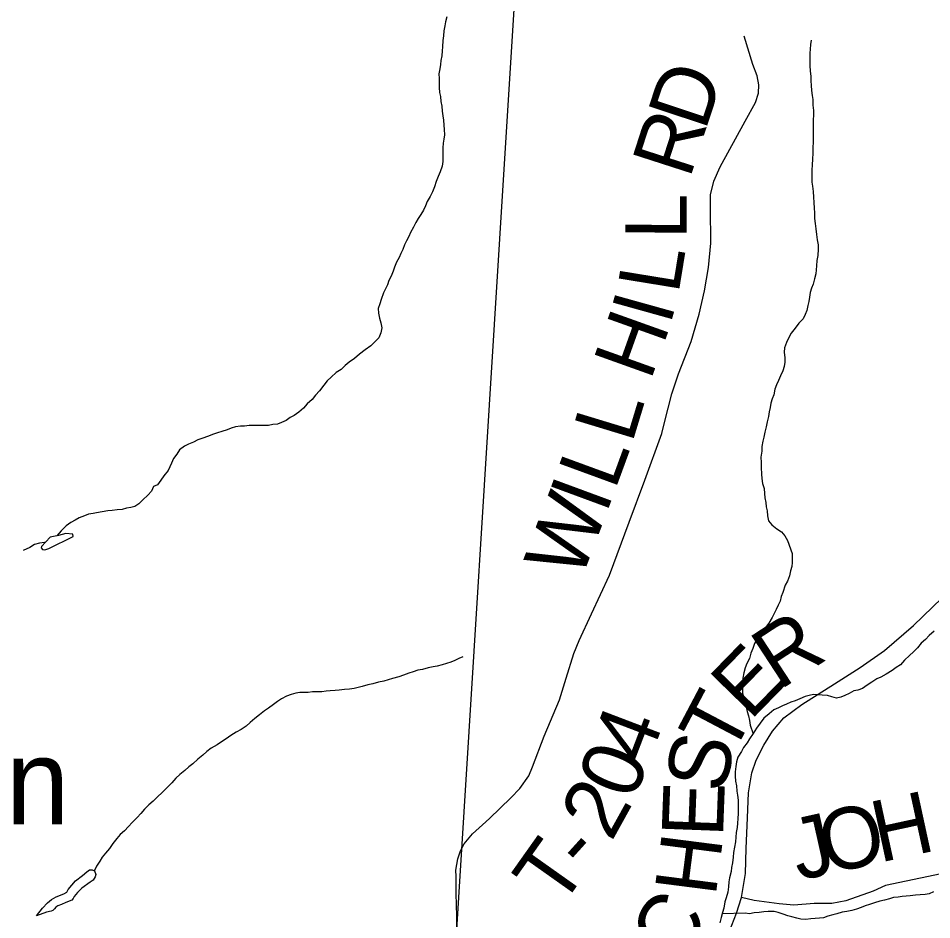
# Model space of a CAD drawing. Extents: x -20.2 to 34, y 0 to 22.
# Drawn here: x 6.324 to 7.17, y 14.988 to 15.823 of the extents above; entities that cross this region are included whole.
import ezdxf

# ---------------------------------------------------------------- set-up
doc = ezdxf.new("R2010")
doc.units = 0
for name, color, linetype in [('GM_X_County_Road_Text', 7, 'Continuous'), ('GM_X_Minor_River', 7, 'Continuous'), ('GM_X_Section', 7, 'Continuous'), ('GM_X_State_Route', 7, 'Continuous'), ('GM_X_Township_Road', 7, 'Continuous'), ('GM_X_Township_Road_Text', 7, 'Continuous'), ('GM_X_Unincorporated_Text', 7, 'Continuous')]:
    doc.layers.add(name, color=color, linetype=linetype)

msp = doc.modelspace()

# ---------------------------------------------------------------- linework, layer by layer
at = {"layer": 'GM_X_Minor_River'}
for points in [[(6.72087, 15.82416), (6.71976, 15.81959), (6.71903, 15.81579), (6.7183, 15.81123), (6.71796, 15.80667), (6.71723, 15.80211), (6.71689, 15.79641), (6.71654, 15.79261), (6.71619, 15.78805), (6.71546, 15.78386), (6.71511, 15.78006), (6.71439, 15.77588), (6.71366, 15.77132), (6.71369, 15.76714), (6.71372, 15.76258), (6.71375, 15.75879), (6.71416, 15.75423), (6.71495, 15.75044), (6.71536, 15.74588), (6.71616, 15.74133), (6.71657, 15.73678), (6.71736, 15.73261)], [(7.05821, 15.80264), (7.05749, 15.79846), (7.05714, 15.79428), (7.05678, 15.79048), (7.05681, 15.78668), (7.05684, 15.78251), (7.05687, 15.77871), (7.05728, 15.77415), (7.0577, 15.76884), (7.05773, 15.76504), (7.05814, 15.76049), (7.05856, 15.75593), (7.05897, 15.75138), (7.05976, 15.74759), (7.0598, 15.74227), (7.06021, 15.73733), (7.06024, 15.73354), (7.0599, 15.7286), (7.05994, 15.72214), (7.05998, 15.7172), (7.06001, 15.71303), (7.06005, 15.70771), (7.0597, 15.70353), (7.05974, 15.69783), (7.0594, 15.69251), (7.05906, 15.68719), (7.05872, 15.68225), (7.05876, 15.67694), (7.0588, 15.67124), (7.05921, 15.66744), (7.06, 15.66251), (7.06042, 15.6572), (7.06046, 15.65226), (7.06088, 15.64695), (7.06129, 15.64277), (7.06133, 15.63745), (7.06174, 15.6329), (7.06254, 15.62797), (7.06295, 15.62265), (7.06375, 15.61772), (7.06454, 15.61317), (7.06457, 15.60899), (7.06424, 15.60329), (7.06351, 15.59873), (7.06317, 15.59379), (7.06281, 15.58999), (7.06246, 15.58619), (7.06136, 15.58162), (7.05988, 15.57667), (7.05839, 15.57286), (7.05727, 15.56906), (7.05655, 15.56449), (7.05582, 15.56069), (7.05508, 15.55689), (7.05398, 15.55232), (7.05249, 15.54851), (7.05062, 15.5447), (7.04685, 15.54049), (7.04347, 15.53591), (7.0397, 15.53133), (7.03708, 15.52675), (7.03521, 15.52256), (7.03335, 15.51761), (7.033, 15.51381), (7.0338, 15.5085), (7.03383, 15.50432), (7.0331, 15.50051), (7.03199, 15.49633), (7.02974, 15.49175), (7.02787, 15.48756), (7.02601, 15.48337), (7.02452, 15.47956), (7.02342, 15.47423), (7.02193, 15.47043), (7.02082, 15.46662), (7.02009, 15.46244), (7.01935, 15.45863), (7.01863, 15.45407), (7.01753, 15.44912), (7.01642, 15.44456), (7.01532, 15.43961), (7.01421, 15.43505), (7.01348, 15.43124), (7.01238, 15.42629), (7.01241, 15.42212), (7.01169, 15.41642), (7.01173, 15.41148), (7.01176, 15.40692), (7.01219, 15.40084), (7.0126, 15.39667), (7.01301, 15.39211), (7.01456, 15.38757), (7.01498, 15.38301), (7.01539, 15.37883), (7.01618, 15.37466), (7.01659, 15.37049), (7.01738, 15.36669), (7.01779, 15.36214), (7.01858, 15.35759), (7.02165, 15.35381), (7.02623, 15.35004)], [(6.71736, 15.73261), (6.71777, 15.72843), (6.71818, 15.72388), (6.71859, 15.7197), (6.71863, 15.71476), (6.71828, 15.71096), (6.71755, 15.70716), (6.7172, 15.70298), (6.71723, 15.6988), (6.71726, 15.69462), (6.71729, 15.69007), (6.71656, 15.68588), (6.71471, 15.68055), (6.71284, 15.67636), (6.71097, 15.67179), (6.70949, 15.66684), (6.70762, 15.66227), (6.70538, 15.6577), (6.70275, 15.65312), (6.70126, 15.64931), (6.69939, 15.64512), (6.69677, 15.6413), (6.69452, 15.63749), (6.69227, 15.63368), (6.69002, 15.62948), (6.68739, 15.62453), (6.6859, 15.62071), (6.68365, 15.6169), (6.68178, 15.61309), (6.6803, 15.6089), (6.67843, 15.60509), (6.67694, 15.60128), (6.67431, 15.59708), (6.67244, 15.59251), (6.67133, 15.58871), (6.66947, 15.58414), (6.66722, 15.57994), (6.66611, 15.57614), (6.66424, 15.57232), (6.66237, 15.56851), (6.66013, 15.56242), (6.65902, 15.55861), (6.65754, 15.55404), (6.65757, 15.54987), (6.65874, 15.54532), (6.65991, 15.54077), (6.66071, 15.53621), (6.65998, 15.53165), (6.65811, 15.52708), (6.65435, 15.52325), (6.65058, 15.51943), (6.64529, 15.51597), (6.64, 15.51176), (6.63547, 15.50793), (6.63056, 15.50447), (6.62679, 15.50141), (6.62302, 15.49758), (6.61848, 15.49489), (6.61396, 15.49068), (6.61018, 15.48723), (6.60718, 15.48303), (6.60304, 15.47807), (6.59927, 15.47386), (6.59626, 15.47004), (6.59174, 15.46583), (6.58835, 15.46201), (6.58382, 15.45818), (6.57966, 15.45511), (6.57588, 15.45318), (6.5721, 15.4505), (6.56794, 15.44857), (6.56416, 15.44702), (6.55998, 15.44661), (6.55581, 15.44582), (6.55201, 15.44579), (6.54708, 15.44576), (6.54252, 15.44572), (6.53796, 15.44569), (6.53379, 15.44528), (6.52999, 15.44525), (6.52544, 15.44446), (6.52128, 15.44329), (6.51749, 15.44175), (6.51256, 15.44019), (6.50877, 15.43903), (6.50499, 15.43786), (6.49931, 15.43554), (6.49514, 15.43399), (6.4906, 15.43244), (6.48643, 15.43051), (6.48189, 15.42858), (6.47811, 15.42665), (6.47358, 15.4232), (6.47095, 15.41938), (6.46794, 15.41518), (6.46607, 15.41099), (6.46309, 15.40413), (6.45895, 15.39916), (6.45632, 15.39535), (6.45331, 15.39077), (6.44953, 15.38922)], [(6.44953, 15.38922), (6.44766, 15.38503), (6.44427, 15.38121), (6.43974, 15.377), (6.43598, 15.37317), (6.4322, 15.37086), (6.4284, 15.37008), (6.42461, 15.36929), (6.42044, 15.36812), (6.41589, 15.36771), (6.41134, 15.3673), (6.40716, 15.36689), (6.40189, 15.36591), (6.3967, 15.36508), (6.39351, 15.36451), (6.38934, 15.36372), (6.3856, 15.36225), (6.38063, 15.36024), (6.37685, 15.35831), (6.37307, 15.356), (6.36853, 15.35293), (6.36401, 15.34834), (6.35987, 15.34375), (6.35995, 15.34382)], [(6.37506, 15.3431), (6.37467, 15.34538), (6.36821, 15.34571), (6.36139, 15.34414), (6.3538, 15.34257), (6.34589, 15.33378), (6.34552, 15.33264), (6.34667, 15.33112), (6.34895, 15.33076), (6.35274, 15.33193), (6.37506, 15.3431)], [(7.02623, 15.35004), (7.03081, 15.34742), (7.03387, 15.34364), (7.03618, 15.33948), (7.04045, 15.32735), (7.04048, 15.32317), (7.04051, 15.319), (7.04016, 15.31519), (7.03905, 15.31139), (7.03794, 15.30682), (7.03608, 15.30187), (7.03421, 15.29806), (7.03198, 15.2912), (7.03049, 15.28739), (7.02939, 15.28321), (7.02751, 15.2794), (7.02564, 15.27559), (7.02377, 15.27177), (7.0219, 15.26796), (7.0189, 15.263), (7.01589, 15.2588), (7.01138, 15.25345), (7.008, 15.24811), (7.00575, 15.24391), (7.00427, 15.23934), (7.0024, 15.23515), (7.00092, 15.2302), (6.99867, 15.22563), (6.99718, 15.22144), (6.9957, 15.21687), (6.99498, 15.21193), (6.99464, 15.20699), (6.99467, 15.20281), (6.9947, 15.19825), (6.99549, 15.19446), (6.99666, 15.18953), (6.99783, 15.18497), (6.999, 15.18118), (7.00017, 15.17701), (7.00096, 15.17284), (7.00175, 15.16829), (7.00433, 15.16051)], [(6.34964, 15.33794), (6.34852, 15.3376), (6.34397, 15.3368), (6.33942, 15.33563), (6.33489, 15.33294), (6.32875, 15.33024)], [(7.17199, 15.25536), (7.16746, 15.25153), (7.16407, 15.2477), (7.15992, 15.24425), (7.15653, 15.24005), (7.15276, 15.23623), (7.14899, 15.23278), (7.14446, 15.22857), (7.1407, 15.22436), (7.13692, 15.22168), (7.13314, 15.21899), (7.12747, 15.21553), (7.12256, 15.21284), (7.11877, 15.21129), (7.11424, 15.20822), (7.11008, 15.20553), (7.10555, 15.20246), (7.10138, 15.20091), (7.09759, 15.20012), (7.09343, 15.19781), (7.08927, 15.19589), (7.08548, 15.19434), (7.08169, 15.19355), (7.07712, 15.19466), (7.07332, 15.19577), (7.06838, 15.19612), (7.0642, 15.19647)], [(6.73586, 15.23173), (6.73207, 15.23018), (6.72829, 15.22825), (6.72451, 15.22671), (6.72072, 15.22554), (6.71655, 15.22437), (6.712, 15.2232), (6.70821, 15.22241), (6.70366, 15.22162), (6.69835, 15.22006), (6.69418, 15.21927), (6.68964, 15.21772), (6.68585, 15.21655), (6.68093, 15.21462), (6.67638, 15.21307), (6.6707, 15.2115), (6.66653, 15.21034), (6.66274, 15.20917), (6.65781, 15.20837), (6.65251, 15.20682), (6.64796, 15.20564), (6.64265, 15.20409), (6.63886, 15.2033), (6.63507, 15.20251), (6.6309, 15.20172), (6.62635, 15.20131), (6.62141, 15.20089), (6.61762, 15.20049), (6.61307, 15.20008), (6.60927, 15.20005), (6.6051, 15.19926), (6.6013, 15.19923), (6.59674, 15.1992), (6.59257, 15.19879), (6.58877, 15.19876), (6.58498, 15.19874), (6.58118, 15.19795), (6.57702, 15.19678), (6.57247, 15.19523), (6.56793, 15.19292), (6.56415, 15.19023), (6.56038, 15.18754), (6.55585, 15.18409), (6.55207, 15.18179), (6.54754, 15.17795), (6.54339, 15.1745), (6.53885, 15.17105), (6.53508, 15.16761), (6.53055, 15.16454), (6.52601, 15.16184), (6.5211, 15.15877), (6.51656, 15.1557), (6.51241, 15.15301), (6.50825, 15.15032), (6.50296, 15.14724), (6.4988, 15.14418), (6.49503, 15.14073), (6.4905, 15.1369), (6.48598, 15.13269), (6.4822, 15.13), (6.47843, 15.12655), (6.4739, 15.12272), (6.47013, 15.11927), (6.46636, 15.11507), (6.46222, 15.11086), (6.45769, 15.10627), (6.45279, 15.10168), (6.44902, 15.09823), (6.44525, 15.09478), (6.4411, 15.09057), (6.43771, 15.08675), (6.43432, 15.08293), (6.4298, 15.07834), (6.42641, 15.07451), (6.42264, 15.07069), (6.41849, 15.06724), (6.41548, 15.06342), (6.41172, 15.05883), (6.40872, 15.05425), (6.40495, 15.05005), (6.40194, 15.04623), (6.39969, 15.04241), (6.39669, 15.03783), (6.39482, 15.03402)], [(7.0642, 15.19647), (7.0604, 15.19682), (7.05623, 15.19603), (7.05244, 15.19486), (7.04752, 15.19293), (7.04336, 15.191), (7.03919, 15.18983), (7.03541, 15.1879), (7.03162, 15.18636), (7.02784, 15.18443), (7.02367, 15.1825), (7.01914, 15.17905), (7.01424, 15.17483), (7.01085, 15.17025), (7.00747, 15.16567), (7.00447, 15.16071), (7.00109, 15.15575), (6.99884, 15.15193), (6.99545, 15.14773), (6.99358, 15.14392), (6.9902, 15.13895), (6.9891, 15.13439), (6.98837, 15.1302), (6.98764, 15.12526), (6.98767, 15.12108), (6.98809, 15.11653), (6.98888, 15.11235), (6.9893, 15.10742), (6.99008, 15.10362), (6.9905, 15.09907), (6.99053, 15.09489), (6.99056, 15.09033), (6.99059, 15.08653), (6.99024, 15.08197), (6.98989, 15.07779), (6.98955, 15.07361), (6.98882, 15.06904), (6.98847, 15.06486), (6.98813, 15.0603), (6.98702, 15.05535), (6.9863, 15.05041), (6.98595, 15.04623), (6.98523, 15.0409), (6.9845, 15.03672), (6.98415, 15.03292), (6.98267, 15.02721), (6.98194, 15.02341), (6.9816, 15.01885), (6.98088, 15.0139), (6.9794, 15.00857), (6.97828, 15.00477), (6.97719, 14.99906), (6.97608, 14.99487), (6.97498, 14.9903), (6.97349, 14.98536)], [(6.34121, 14.99185), (6.34685, 14.9991), (6.35137, 15.00407), (6.35514, 15.00714), (6.3593, 15.00945), (6.3665, 15.01216), (6.36915, 15.0137), (6.37064, 15.01637), (6.37742, 15.0244), (6.38384, 15.02938), (6.38764, 15.03269), (6.39026, 15.03437), (6.3926, 15.03446), (6.39482, 15.03364), (6.39599, 15.03023), (6.39562, 15.02795), (6.39375, 15.02489), (6.39072, 15.02297), (6.38317, 15.0176), (6.37902, 15.01339), (6.37601, 15.00995), (6.37526, 15.00804), (6.37376, 15.00651), (6.36846, 15.0042), (6.36429, 15.00227), (6.36096, 15.00104), (6.35907, 15.0001), (6.35787, 14.99842), (6.35623, 14.99691), (6.35485, 14.99612), (6.3503, 14.99533), (6.34121, 14.99185)], [(7.17149, 15.01412), (7.16733, 15.01219), (7.16354, 15.01179), (7.15898, 15.01137), (7.15481, 15.01096), (7.14988, 15.01055), (7.14608, 15.01014), (7.14229, 15.00974), (7.13849, 15.00933), (7.13432, 15.00892), (7.13053, 15.00775), (7.12598, 15.00658), (7.12182, 15.00541), (7.11689, 15.00386), (7.11197, 15.0023), (7.10818, 15.00113), (7.10439, 14.99959), (7.10023, 14.99804), (7.09568, 14.99687), (7.09113, 14.99607), (7.08696, 14.99528), (7.08203, 14.99373), (7.07824, 14.99294), (7.07369, 14.99177), (7.06953, 14.99022), (7.06573, 14.98981), (7.06194, 14.98941), (7.05776, 14.989), (7.05321, 14.98858), (7.04865, 14.98893), (7.04485, 14.98966), (7.04028, 14.99115), (7.03648, 14.99188), (7.03229, 14.99337), (7.02772, 14.99486), (7.02392, 14.99597), (7.01822, 14.99593), (7.01443, 14.99553), (7.00987, 14.99511), (7.00532, 14.9947), (7.00115, 14.99391), (6.99697, 14.99426), (6.9758, 14.99371)]]:
    msp.add_lwpolyline(points, dxfattribs=at)
at = {"layer": 'GM_X_Section'}
msp.add_lwpolyline([(6.79044, 15.94473), (7.86237, 15.87982), (7.79854, 14.87534), (6.72741, 14.93458), (6.77473, 15.69297)], close=True, dxfattribs=at)
at = {"layer": 'GM_X_State_Route'}
for points in [[(6.99364, 15.00887), (6.99749, 15.03099), (6.99811, 15.05429), (6.99915, 15.08279), (6.99998, 15.10567), (7.0031, 15.12418), (7.00727, 15.13605), (7.01434, 15.14977), (7.02224, 15.16288), (7.03285, 15.17515), (7.04949, 15.18764), (7.07966, 15.20656), (7.10358, 15.22175), (7.12605, 15.23756), (7.15291, 15.26065), (7.19678, 15.30288)], [(6.76226, 14.86085), (6.81156, 14.86754), (6.83594, 14.87041), (6.86415, 14.87629), (6.88758, 14.8841), (6.90338, 14.89172), (6.92172, 14.90317), (6.93716, 14.91534), (6.94262, 14.92066), (6.95168, 14.9295), (6.96386, 14.94494), (6.97384, 14.96019), (6.98256, 14.97763), (6.9891, 14.99434), (6.99364, 15.00887)]]:
    msp.add_lwpolyline(points, dxfattribs=at)
at = {"layer": 'GM_X_Township_Road'}
for points in [[(6.92235, 15.44859), (6.92902, 15.47512), (6.9354, 15.4937), (6.94703, 15.52354), (6.95454, 15.54887), (6.95941, 15.57045), (6.96317, 15.59222), (6.96524, 15.61456), (6.96486, 15.6474), (6.96504, 15.65941), (6.96805, 15.67198), (6.97387, 15.6853), (6.99714, 15.72753), (7.00652, 15.74479), (7.00934, 15.75361), (7.00971, 15.76111), (7.00802, 15.76956), (7.00408, 15.78007), (6.9962, 15.80634)], [(6.75405, 15.07625), (6.7605, 15.08217), (6.78021, 15.10112), (6.78865, 15.10975), (6.79691, 15.12157), (6.8001, 15.12983), (6.81098, 15.15835), (6.82524, 15.19176), (6.83124, 15.21184), (6.83838, 15.23492), (6.84344, 15.24674), (6.8547, 15.27151), (6.87159, 15.30736), (6.8898, 15.35633), (6.90406, 15.39518), (6.91982, 15.43853), (6.92235, 15.44859)], [(6.72945, 15.02829), (6.72935, 15.03412), (6.73104, 15.04464), (6.73348, 15.05214), (6.73694, 15.05859), (6.74474, 15.06771), (6.75405, 15.07625)], [(6.76226, 14.86085), (6.75355, 14.86767), (6.74717, 14.87142), (6.73967, 14.87405), (6.73422, 14.87743), (6.72953, 14.88174), (6.72705, 14.88612), (6.72634, 14.88737), (6.72353, 14.89432), (6.72203, 14.90464), (6.72316, 14.91215), (6.72785, 14.92866), (6.72991, 14.94067), (6.73028, 14.95925), (6.7301, 14.99171), (6.72973, 15.01273), (6.72945, 15.02829)], [(7.17853, 15.03084), (7.12695, 15.01995), (7.11551, 15.01486), (7.09008, 15.00578), (7.07719, 15.00342), (7.06102, 15.00342), (7.04207, 15.00191), (7.02851, 15.00305), (7.00527, 15.00614), (6.99364, 15.00887)]]:
    msp.add_lwpolyline(points, dxfattribs=at)

# ---------------------------------------------------------------- texts
at = {"layer": 'GM_X_County_Road_Text'}
for s, rotation, p in [('R', 33.17047, (7.02869, 15.20022)), ('E', 45.74547, (7.00157, 15.17187)), ('T', 62.17758, (6.98426, 15.13776)), ('S', 78.02935, (6.97772, 15.10415)), ('E', 87.85381, (6.97645, 15.06423)), ('H', 82.71682, (6.96965, 15.00909)), ('C', 57.24741, (6.93504, 14.94414))]:
    msp.add_text(s, height=0.05682, rotation=rotation, dxfattribs=at).set_placement(p)
at = {"layer": 'GM_X_Township_Road_Text'}
for s, rotation, p in [('D', 71.66411, (6.95995, 15.71756)), ('R', 72.11183, (6.94565, 15.67326)), ('L', 89.78095, (6.94286, 15.61815)), ('L', 80.71304, (6.93519, 15.56659)), ('I', 74.42909, (6.92749, 15.53758)), ('H', 70.29202, (6.9093, 15.48632)), ('L', 73.07951, (6.89218, 15.42821)), ('L', 69.87734, (6.87648, 15.38507)), ('I', 69.73174, (6.86834, 15.36304)), ('W', 69.08225, (6.84459, 15.30089)), ('4', 69.14453, (6.90668, 15.13078)), ('0', 68.35648, (6.89346, 15.09745)), ('2', 61.06098, (6.87316, 15.0597)), ('H', 12.22298, (7.12117, 15.04103)), ('O', 12.5943, (7.07247, 15.03015)), ('J', 12.59326, (7.04644, 15.02434)), ('T', 54.67654, (6.8258, 14.99754)), ('-', 47.89906, (6.84926, 15.03083))]:
    msp.add_text(s, height=0.05682, rotation=rotation, dxfattribs=at).set_placement(p)
at = {"layer": 'GM_X_Unincorporated_Text'}
msp.add_text('Browntown', height=0.078977, rotation=0.00001, dxfattribs=at).set_placement((5.84916, 15.07672))

doc.saveas('drawing.dxf')
